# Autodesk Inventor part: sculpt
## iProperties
Created: 2006-03
Part Number: sculpt
Document SubType Name: Modeling
Designer: Administrator
Density: 1 g/cm^3
Author: Administrator
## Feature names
1. Extrusion1
